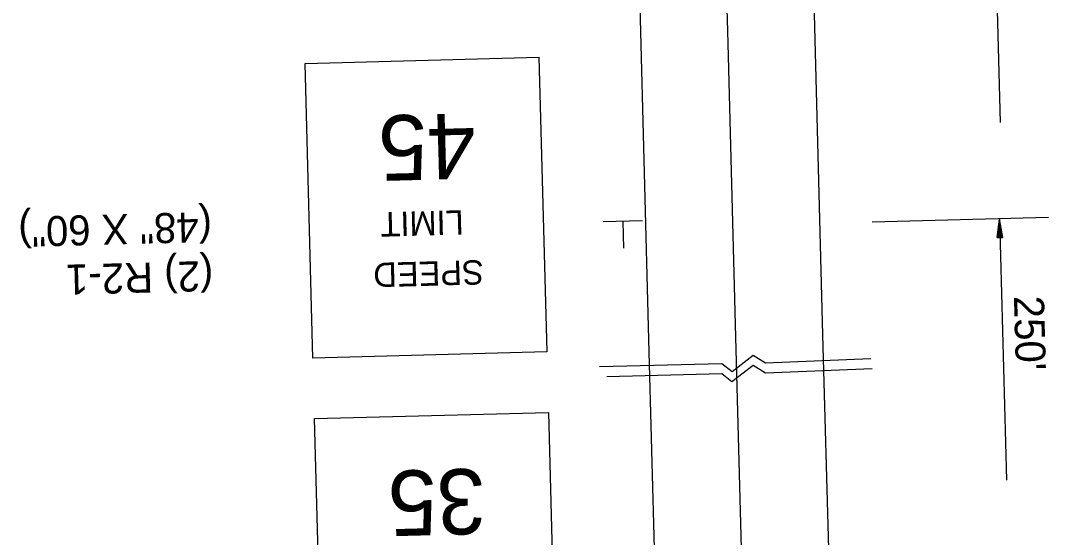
# Model space of a CAD drawing. Extents: x 1929624 to 1935547, y 596315 to 605721.
# Drawn here: x 1931200.9 to 1931406.2, y 597212.7 to 597315.9 of the extents above; entities that cross this region are included whole.
import ezdxf

# ---------------------------------------------------------------- set-up
doc = ezdxf.new("R2010")
doc.units = 0
doc.layers.add('Default', color=7, linetype='Continuous')

msp = doc.modelspace()

# ---------------------------------------------------------------- linework, layer by layer
at = {"layer": 'Default'}
for p, q in [((1931341.06, 597352.78), (1931342.1, 597313.86)), ((1931395.16, 597347.72), (1931396.56, 597295.55)), ((1931359.34, 597319.77), (1931361.12, 597253.18)), ((1931324.58, 597318.78), (1931326.37, 597252.24)), ((1931342.1, 597313.86), (1931343.74, 597252.71)), ((1931406.22, 597276.6), (1931371.02, 597275.66)), ((1931317.3, 597275.8), (1931325.12, 597276.01)), ((1931321.19, 597275.79), (1931321.34, 597270.45)), ((1931395.97, 597272.57), (1931396.43, 597276.34)), ((1931396.06, 597272.58), (1931396.45, 597275.71)), ((1931396.16, 597272.58), (1931396.47, 597275.07)), ((1931396.25, 597272.58), (1931396.48, 597274.44)), ((1931396.43, 597276.34), (1931397.83, 597224.17)), ((1931397.1, 597272.6), (1931396.43, 597276.34)), ((1931397, 597272.6), (1931396.45, 597275.71)), ((1931396.91, 597272.6), (1931396.47, 597275.07)), ((1931396.81, 597272.6), (1931396.48, 597274.44)), ((1931395.97, 597272.57), (1931397.1, 597272.6)), ((1931396.35, 597272.58), (1931396.5, 597273.81)), ((1931396.44, 597272.59), (1931396.52, 597273.18)), ((1931396.72, 597272.59), (1931396.5, 597273.81)), ((1931396.62, 597272.59), (1931396.52, 597273.18)), ((1931326.37, 597252.24), (1931328.22, 597183.26)), ((1931343.74, 597252.71), (1931345.6, 597183.73)), ((1931361.12, 597253.18), (1931362.97, 597184.2))]:
    msp.add_line(p, q, dxfattribs=at)
for points in [[(1931259.32, 597248.51), (1931257.74, 597307.35), (1931304.43, 597308.61), (1931306.01, 597249.76)], [(1931261.23, 597177.58), (1931259.65, 597236.43), (1931306.34, 597237.68), (1931307.92, 597178.83)]]:
    msp.add_lwpolyline(points, close=True, dxfattribs=at)
for points in [[(1931370.75, 597248.39), (1931349.73, 597247.5), (1931347.28, 597249.06), (1931343.03, 597245.78), (1931340.99, 597247.39), (1931316.54, 597246.74)], [(1931371, 597246.4), (1931349.7, 597245.5), (1931347.25, 597247.06), (1931343, 597243.78), (1931340.96, 597245.39), (1931318, 597244.78)]]:
    msp.add_lwpolyline(points, dxfattribs=at)

# ---------------------------------------------------------------- texts
for s, height, rotation, p in [('45', 13.039, 181.5377, (1931291.67, 597297.41)), ('(48" X 60")', 6, 181.5377, (1931239.09, 597277.72)), ('LIMIT', 4.865, 181.5377, (1931289.37, 597278.05)), ('(2) R2-1', 6, 181.5377, (1931239.35, 597267.94)), ('SPEED', 4.865, 181.5377, (1931293.37, 597268.1)), ("250'", 6, 271.5377, (1931399.32, 597260.88)), ('35', 13.039, 181.5377, (1931293.58, 597226.49))]:
    msp.add_text(s, height=height, rotation=rotation, dxfattribs=at).set_placement(p)

doc.saveas('drawing.dxf')
